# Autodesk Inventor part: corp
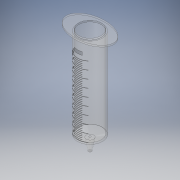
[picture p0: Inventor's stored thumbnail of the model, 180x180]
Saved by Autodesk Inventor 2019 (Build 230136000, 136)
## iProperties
Created: 2020-11
Part Number: corp
Material: PET Plastic
Document SubType Name: Modeling
Designer: bianc
Density: 1.541 g/cm^3
Appearance: Polycarbonate - Clear
Author: bianc
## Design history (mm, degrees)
sketch "Sketch1"
  geometry: L1 (0, 0)-(0, 27.445); L2 (-7.938, 59.302)-(-7.938, 2.152); L3 (0, 0)-(-18.678, 0); L4 (-7.144, 59.302)-(-7.144, 2.76); L5 (-2.341, 0.635)-(-7.938, 2.152); L6 (-7.144, 2.76)-(0, 0.823); L7 (-7.938, 59.302)-(19.176, 59.302); L8 (0, 0.823)-(0, -6.971); L9 (0, -6.971)-(-1, -6.971); L10 (-1, -6.971)-(-2.341, 0.635)
  constraints: 20 end point, 3 vertical, 2 horizontal, 2 perpendicular, 2 point on line, 1 parallel
  dimensions: "d0" = 7.938 distance between parallel lines of L2 L1; "d2" = 7.144 distance between parallel lines of L4 L1; "d3" = 0.794 distance between parallel lines of L4 L2 (derived); "d4" = 74.83 deg angle of L1 L5; "d5" = 0.794 distance between parallel lines of L6 L5; "d6" = 57.15 distance of L2.start L2.end; "d7" = 7.794 distance of L6.end L8.end; "d8" = 1 distance of L8.end L9.end; "d9" = 100 deg angle of L9 L10
revolve "Revolution1" sketch "Sketch1" stored, may be unused: angle "d10" = 90 deg
sketch "Sketch2"
  geometry: 3 further points
  constraints: 2 coincident
hole "Hole1" sketch "Sketch2" at (0, 0) diameter "d11" = 1.25; stored, may be unused: countersink angle "d15" = 90 deg, drill point angle "d17" = 118 deg; dims "d12" = 6, "d13" = 4, "d14" = 2, "d16" = 8
sketch "Sketch3"
  geometry: L1 (18.381, -9.525)-(-15.081, -9.525); L2 (-15.081, -12.061)-(-15.081, 8.255); C1 r 7.153 at (0, 0); C2 r 0.625 at (0, 0) reference; 2 further points; 1 other entity
  constraints: 4 end point, 2 coincident, 2 horizontal, 1 centre point, 1 point on line, 1 vertical, 2 other
  dimensions: "d18" = 9.525 distance from line of L1 point (0, 0); "d19" = 15.081 distance from line of L2 point (0, 0)
extrude "Extrusion1" join sketch "Sketch3" distance "d20" = 1; taper "d21" = 0 deg
workplane "Work Plane6"
  workplane "Work Plane5"
sketch "Sketch5" dims "d254" = 10, "d268" = 10
  geometry: L1 (57.15, 15.876)-(57.15, 0) reference; L2 (57.15, 0)-(57.15, 15.876); L3 (57.15, 7.917)-(4.866, 7.917); L4 (56.05, 2.917)-(56.15, 2.917); L5 (56.15, 2.917)-(56.15, 12.917); L6 (56.15, 12.917)-(56.05, 12.917); L7 (56.05, 12.917)-(56.05, 2.917); L8 (55.05, 5.417)-(55.15, 5.417); L9 (55.15, 5.417)-(55.15, 10.417); L10 (55.15, 10.417)-(55.05, 10.417); L11 (55.05, 10.417)-(55.05, 5.417); L12 (56.15, 7.917)-(3.866, 7.917); L13 (54.05, 5.417)-(54.15, 5.417); L14 (54.15, 5.417)-(54.15, 10.417); L15 (54.15, 10.417)-(54.05, 10.417); L16 (54.05, 10.417)-(54.05, 5.417); L17 (55.15, 7.917)-(2.866, 7.917); L18 (53.05, 5.417)-(53.15, 5.417); L19 (53.15, 5.417)-(53.15, 10.417); L20 (53.15, 10.417)-(53.05, 10.417); L21 (53.05, 10.417)-(53.05, 5.417); L22 (54.15, 7.917)-(1.866, 7.917); L23 (52.05, 5.417)-(52.15, 5.417); L24 (52.15, 5.417)-(52.15, 10.417); L25 (52.15, 10.417)-(52.05, 10.417); L26 (52.05, 10.417)-(52.05, 5.417); L27 (51.05, 2.917)-(51.15, 2.917); L28 (50.05, 5.417)-(50.15, 5.417); L29 (51.15, 12.917)-(51.05, 12.917); L30 (49.05, 5.417)-(49.15, 5.417); L31 (48.05, 5.417)-(48.15, 5.417); L32 (47.05, 5.417)-(47.15, 5.417); L33 (51.15, 2.917)-(51.15, 12.917); L34 (51.05, 12.917)-(51.05, 2.917); L35 (50.15, 5.417)-(50.15, 10.417); L36 (50.05, 10.417)-(50.05, 5.417); L37 (49.15, 5.417)-(49.15, 10.417); L38 (49.05, 10.417)-(49.05, 5.417); L39 (48.05, 10.417)-(48.05, 5.417); L40 (47.15, 5.417)-(47.15, 10.417); L41 (47.05, 10.417)-(47.05, 5.417); L42 (52.15, 7.917)-(-0.134, 7.917); L43 (51.15, 7.917)-(-1.134, 7.917); L44 (50.15, 7.917)-(-2.134, 7.917); L45 (49.15, 7.917)-(-3.134, 7.917); L46 (48.15, 5.417)-(48.15, 10.417); L47 (50.15, 10.417)-(50.05, 10.417); L48 (49.15, 10.417)-(49.05, 10.417); L49 (48.15, 10.417)-(48.05, 10.417); L50 (47.15, 10.417)-(47.05, 10.417); L51 (46.05, 2.917)-(46.15, 2.917); L52 (45.05, 5.417)-(45.15, 5.417); L53 (46.15, 12.917)-(46.05, 12.917); L54 (44.05, 5.417)-(44.15, 5.417); L55 (43.05, 5.417)-(43.15, 5.417); L56 (42.05, 5.417)-(42.15, 5.417); L57 (46.15, 2.917)-(46.15, 12.917); L58 (46.05, 12.917)-(46.05, 2.917); L59 (45.15, 5.417)-(45.15, 10.417); L60 (45.05, 10.417)-(45.05, 5.417); L61 (44.15, 5.417)-(44.15, 10.417); L62 (44.05, 10.417)-(44.05, 5.417); L63 (43.05, 10.417)-(43.05, 5.417); L64 (42.15, 5.417)-(42.15, 10.417)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; 2 further points
  constraints: 460 end point, 9 equal length, 7 horizontal, 4 perpendicular, 3 collinear, 3 point on line, 2 coincident, 483 other
  dimensions: "d244" = 10 distance of L4.end L5.end; "d245" = 5 distance between parallel lines of L3 L4; "d246" = 0.1 distance of L5.end L6.end; "d247" = 1 distance between parallel lines of L5 L1; "d248" = 5 distance of L8.end L9.end; "d249" = 2.5 distance between parallel lines of L3 L8; "d250" = 0.1 distance of L9.end L10.end; "d251" = 1 distance between parallel lines of L9 L5; "d257" = 1 distance of L3.start L12.start; "d264" = 5 distance of L8.end L28.end; "d271" = 45 distance of L6.end L219.end; "d381" = 5 distance of L264.end L265.end; "d382" = 2 distance of L264.start L264.end; "d383" = 2.5 distance between parallel lines of L3 L264; "d384" = 0.1 distance between parallel lines of L267 L271
emboss "Emboss2" sketch "Sketch5" dims "d18" = 9.525, "d19" = 15.081, "d385" = 0.1, "d386" = 0
body "Solid1"
other parameters: "d243" = 15
